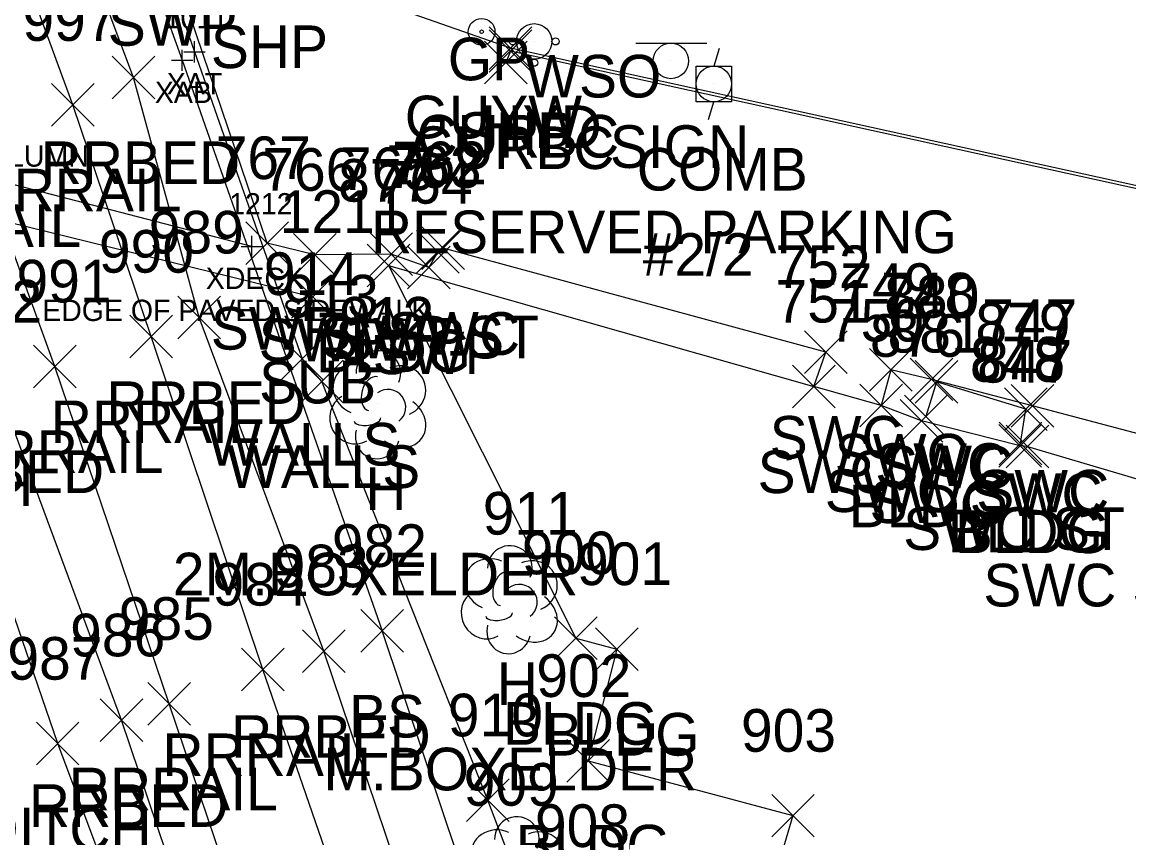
# Model space of a CAD drawing. Extents: x 1462668 to 1465147, y 550359 to 557351.
# Drawn here: x 1464802.6 to 1464854.5, y 552350.4 to 552388.6 of the extents above; entities that cross this region are included whole.
import ezdxf

# ---------------------------------------------------------------- set-up
doc = ezdxf.new("R2010")
doc.units = 0
for name, color, linetype in [('B_A', 7, 'Continuous'), ('B_C', 7, 'Continuous'), ('B_I', 7, 'Continuous'), ('B_TIC', 7, 'Continuous'), ('BELB', 7, 'Continuous'), ('BSUBM', 7, 'Continuous'), ('D_A', 7, 'Continuous'), ('D_I', 7, 'Continuous'), ('D_TIC', 7, 'Continuous'), ('DD', 7, 'Continuous'), ('L_A', 7, 'Continuous'), ('L_C', 7, 'Continuous'), ('L_I', 7, 'Continuous'), ('L_TIC', 7, 'Continuous'), ('LBC', 7, 'Continuous'), ('LELB', 7, 'Continuous'), ('LTD', 7, 'Continuous'), ('LWS', 7, 'Continuous'), ('P_A', 7, 'Continuous'), ('P_TIC', 7, 'Continuous'), ('PSP', 7, 'Continuous'), ('R_A', 7, 'Continuous'), ('R_I', 7, 'Continuous'), ('R_TIC', 7, 'Continuous'), ('RC', 7, 'Continuous'), ('RR', 7, 'Continuous'), ('RRB', 7, 'Continuous'), ('RSW', 7, 'Continuous'), ('S_A', 7, 'Continuous'), ('S_C', 7, 'Continuous'), ('SSGN', 7, 'Continuous'), ('U_A', 7, 'Continuous'), ('U_C', 7, 'Continuous'), ('U_I', 7, 'Continuous'), ('U_TIC', 7, 'Continuous'), ('UP', 7, 'Continuous'), ('UPGW', 7, 'Continuous'), ('UUU', 7, 'Continuous'), ('UWFH', 7, 'Continuous')]:
    doc.layers.add(name, color=color, linetype=linetype)

msp = doc.modelspace()

# ---------------------------------------------------------------- linework, layer by layer
at = {"layer": 'B_TIC'}
for p, q in [((1464810.703, 552387.236), (1464810.778, 552387.236)), ((1464810.127, 552386.833), (1464810.203, 552386.833)), ((1464813.397, 552378.102), (1464813.472, 552378.102))]:
    msp.add_line(p, q, dxfattribs=at)
for points in [[(1464810.699, 552386.736), (1464810.699, 552387.736)], [(1464810.124, 552386.333), (1464810.124, 552387.333)], [(1464810.199, 552387.236), (1464811.199, 552387.236)], [(1464809.624, 552386.833), (1464810.624, 552386.833)], [(1464813.393, 552377.602), (1464813.393, 552378.602)], [(1464812.893, 552378.102), (1464813.893, 552378.102)]]:
    msp.add_lwpolyline(points, dxfattribs=at)
at = {"layer": 'BELB'}
msp.add_lwpolyline([(1464813.393, 552378.102), (1464799.823, 552381.621), (1464785.51, 552385.077)], dxfattribs=at)
at = {"layer": 'BSUBM'}
for points in [[(1464775.683, 552477.42), (1464775.939, 552477.572), (1464781.431, 552465.945), (1464796.582, 552427.88), (1464810.699, 552387.236)], [(1464775.683, 552477.42), (1464795.526, 552427.291), (1464810.124, 552386.833)], [(1464810.699, 552387.236), (1464815.756, 552372.822)], [(1464810.124, 552386.833), (1464819.514, 552360.064)]]:
    msp.add_lwpolyline(points, dxfattribs=at)
at = {"layer": 'D_TIC'}
for points in [[(1464803.285, 552353.776), (1464805.285, 552355.776)], [(1464805.285, 552353.776), (1464803.285, 552355.776)]]:
    msp.add_lwpolyline(points, dxfattribs=at)
at = {"layer": 'DD'}
msp.add_lwpolyline([(1464838.938, 552245.842), (1464832.309, 552266.963), (1464825.398, 552292.253), (1464817.853, 552318.608), (1464804.285, 552354.776), (1464798.736, 552370.918), (1464794.981, 552381.157)], dxfattribs=at)
at = {"layer": 'L_TIC'}
for points in [[(1464818.808, 552376.202), (1464820.808, 552378.202)], [(1464820.808, 552376.202), (1464818.808, 552378.202)], [(1464814.756, 552371.822), (1464816.756, 552373.822)], [(1464816.756, 552371.822), (1464814.756, 552373.822)], [(1464815.686, 552370.77), (1464817.686, 552372.77)], [(1464817.686, 552370.77), (1464815.686, 552372.77)], [(1464843.815, 552368.925), (1464845.815, 552370.925)], [(1464845.815, 552368.925), (1464843.815, 552370.925)], [(1464848.453, 552367.748), (1464850.453, 552369.748)], [(1464850.453, 552367.748), (1464848.453, 552369.748)], [(1464848.793, 552367.713), (1464850.793, 552369.713)], [(1464850.793, 552367.713), (1464848.793, 552369.713)], [(1464818.514, 552359.064), (1464820.514, 552361.064)], [(1464820.514, 552359.064), (1464818.514, 552361.064)], [(1464827.593, 552358.721), (1464829.593, 552360.721)], [(1464829.593, 552358.721), (1464827.593, 552360.721)], [(1464829.526, 552358.213), (1464831.526, 552360.213)], [(1464831.526, 552358.213), (1464829.526, 552360.213)], [(1464828.183, 552352.965), (1464830.183, 552354.965)], [(1464830.183, 552352.965), (1464828.183, 552354.965)], [(1464823.474, 552351.117), (1464825.474, 552353.117)], [(1464825.474, 552351.117), (1464823.474, 552353.117)], [(1464837.788, 552350.396), (1464839.788, 552352.396)], [(1464839.788, 552350.396), (1464837.788, 552352.396)]]:
    msp.add_lwpolyline(points, dxfattribs=at)
at = {"layer": 'LBC'}
for points in [[(1464819.808, 552377.202), (1464828.593, 552359.721), (1464830.526, 552359.213), (1464829.183, 552353.965), (1464838.788, 552351.396), (1464836.379, 552343.209), (1464841.14, 552341.464)], [(1464819.808, 552377.202), (1464839.766, 552371.53)], [(1464844.815, 552369.925), (1464842.92, 552370.641)], [(1464849.793, 552368.713), (1464849.453, 552368.748), (1464844.815, 552369.925)], [(1464849.793, 552368.713), (1464858.257, 552366.213)]]:
    msp.add_lwpolyline(points, dxfattribs=at)
at = {"layer": 'LELB'}
msp.add_lwpolyline([(1464854.329, 552250.98), (1464847.618, 552272.797), (1464840.374, 552296.612), (1464833.437, 552323.254), (1464825.847, 552341.173), (1464819.514, 552360.064)], dxfattribs=at)
at = {"layer": 'LTD'}
for p, q in [((1464819.287, 552370.731), (1464819.287, 552370.731)), ((1464819.287, 552370.731), (1464819.287, 552370.731)), ((1464825.458, 552361.583), (1464825.458, 552361.583)), ((1464825.458, 552361.583), (1464825.458, 552361.583))]:
    msp.add_line(p, q, dxfattribs=at)
for centre in [(1464819.333, 552372.165), (1464825.505, 552363.017), (1464825.83, 552350.298)]:
    msp.add_arc(centre, 1.047, 335.5272, 180.9563, dxfattribs=at)
for centre, major_axis, ratio, start_param, end_param in [((1464818.495, 552371.398), (1.21, -0.512), 0.895232, 1.570796, 4.712389), ((1464820.328, 552371.315), (-1.141, -0.483), 0.949671, 1.570796, 4.712389), ((1464819.078, 552371.19), (-0.208, -0.792), 0.645439, 3.141593, 6.283185), ((1464818.203, 552370.023), (0.584, -1.042), 0.959034, 3.141593, 6.283185), ((1464819.787, 552370.565), (-0.5, 0.667), 0.989748, 3.141593, 6.283185), ((1464820.287, 552369.898), (-1.09, 0.792), 0.841452, 1.570796, 4.712389), ((1464818.828, 552369.981), (-0.625, -0.083), 0.423636, 0, 3.141593), ((1464819.287, 552369.231), (0.265, 1.061), 0.942809, 1.570796, 4.712389), ((1464824.666, 552362.25), (1.21, -0.512), 0.895232, 1.570796, 4.712389), ((1464826.5, 552362.167), (-1.141, -0.483), 0.949671, 1.570796, 4.712389), ((1464825.25, 552362.041), (-0.208, -0.792), 0.645439, 3.141593, 6.283185), ((1464825.958, 552361.417), (-0.5, 0.667), 0.989748, 3.141593, 6.283185), ((1464824.375, 552360.875), (0.584, -1.042), 0.959034, 3.141593, 6.283185), ((1464826.458, 552360.75), (-1.09, 0.792), 0.841452, 1.570796, 4.712389), ((1464825, 552360.833), (-0.625, -0.083), 0.423636, 0, 3.141593), ((1464825.458, 552360.083), (0.265, 1.061), 0.942809, 1.570796, 4.712389), ((1464824.991, 552349.53), (1.21, -0.512), 0.895232, 1.570796, 4.712389), ((1464826.825, 552349.447), (-1.141, -0.483), 0.949671, 1.570796, 4.712389)]:
    msp.add_ellipse(centre, major_axis=major_axis, ratio=ratio, start_param=start_param, end_param=end_param, dxfattribs=at)
at = {"layer": 'LWS'}
msp.add_lwpolyline([(1464855.198, 552255.3), (1464847.558, 552276.515), (1464841.664, 552299.914), (1464835.533, 552322.98), (1464835.365, 552323.51), (1464828.08, 552342.622), (1464824.474, 552352.117), (1464816.686, 552371.77), (1464815.756, 552372.822)], dxfattribs=at)
at = {"layer": 'P_TIC'}
for points in [[(1464824.527, 552386.397), (1464826.527, 552388.397)], [(1464826.527, 552386.397), (1464824.527, 552388.397)]]:
    msp.add_lwpolyline(points, dxfattribs=at)
at = {"layer": 'PSP'}
msp.add_lwpolyline([(1464948.464, 552361.284), (1464924.269, 552366.192), (1464895.316, 552372.264), (1464865.11, 552378.716), (1464825.527, 552387.397), (1464813.937, 552391.469)], dxfattribs=at)
at = {"layer": 'R_TIC'}
for points in [[(1464824.539, 552386.27), (1464826.539, 552388.27)], [(1464826.539, 552386.27), (1464824.539, 552388.27)], [(1464824.315, 552385.733), (1464826.315, 552387.733)], [(1464826.315, 552385.733), (1464824.315, 552387.733)], [(1464806.843, 552385.028), (1464808.843, 552387.028)], [(1464808.843, 552385.028), (1464806.843, 552387.028)], [(1464803.992, 552383.746), (1464805.992, 552385.746)], [(1464805.992, 552383.746), (1464803.992, 552385.746)], [(1464813.11, 552377.261), (1464815.11, 552379.261)], [(1464815.11, 552377.261), (1464813.11, 552379.261)], [(1464821.12, 552376.849), (1464823.12, 552378.849)], [(1464823.12, 552376.849), (1464821.12, 552378.849)], [(1464821.378, 552377.018), (1464823.378, 552379.018)], [(1464823.378, 552377.018), (1464821.378, 552379.018)], [(1464815.353, 552376.713), (1464817.353, 552378.713)], [(1464817.353, 552376.713), (1464815.353, 552378.713)], [(1464818.941, 552376.744), (1464820.941, 552378.744)], [(1464820.941, 552376.744), (1464818.941, 552378.744)], [(1464820.704, 552376.109), (1464822.704, 552378.109)], [(1464822.704, 552376.109), (1464820.704, 552378.109)], [(1464809.928, 552373.769), (1464811.928, 552375.769)], [(1464811.928, 552373.769), (1464809.928, 552375.769)], [(1464807.668, 552372.872), (1464809.668, 552374.872)], [(1464809.668, 552372.872), (1464807.668, 552374.872)], [(1464839.333, 552372.146), (1464841.333, 552374.146)], [(1464841.333, 552372.146), (1464839.333, 552374.146)], [(1464803.149, 552371.473), (1464805.149, 552373.473)], [(1464805.149, 552371.473), (1464803.149, 552373.473)], [(1464842.383, 552371.308), (1464844.383, 552373.308)], [(1464844.383, 552371.308), (1464842.383, 552373.308)], [(1464844.283, 552370.866), (1464846.283, 552372.866)], [(1464846.283, 552370.866), (1464844.283, 552372.866)], [(1464844.519, 552370.754), (1464846.519, 552372.754)], [(1464846.519, 552370.754), (1464844.519, 552372.754)], [(1464838.766, 552370.53), (1464840.766, 552372.53)], [(1464840.766, 552370.53), (1464838.766, 552372.53)], [(1464841.92, 552369.641), (1464843.92, 552371.641)], [(1464843.92, 552369.641), (1464841.92, 552371.641)], [(1464849.027, 552369.62), (1464851.027, 552371.62)], [(1464851.027, 552369.62), (1464849.027, 552371.62)], [(1464844.021, 552369.124), (1464846.021, 552371.124)], [(1464846.021, 552369.124), (1464844.021, 552371.124)], [(1464848.716, 552369.461), (1464850.716, 552371.461)], [(1464850.716, 552369.461), (1464848.716, 552371.461)], [(1464848.463, 552367.862), (1464850.463, 552369.862)], [(1464850.463, 552367.862), (1464848.463, 552369.862)], [(1464815.78, 552358.11), (1464817.78, 552360.11)], [(1464817.78, 552358.11), (1464815.78, 552360.11)], [(1464812.909, 552357.251), (1464814.909, 552359.251)], [(1464814.909, 552357.251), (1464812.909, 552359.251)], [(1464808.517, 552355.645), (1464810.517, 552357.645)], [(1464810.517, 552355.645), (1464808.517, 552357.645)], [(1464806.286, 552354.87), (1464808.286, 552356.87)], [(1464808.286, 552354.87), (1464806.286, 552356.87)]]:
    msp.add_lwpolyline(points, dxfattribs=at)
at = {"layer": 'RC'}
msp.add_lwpolyline([(1464948.184, 552360.613), (1464948.268, 552361.112), (1464924.278, 552366.019), (1464895.338, 552372.102), (1464864.961, 552378.598), (1464825.539, 552387.27), (1464825.315, 552386.733)], dxfattribs=at)
at = {"layer": 'RR'}
for points in [[(1464849.389, 552249.534), (1464842.819, 552270.793), (1464835.11, 552294.838), (1464826.262, 552322.52), (1464813.909, 552358.251), (1464808.668, 552373.872), (1464804.992, 552384.746), (1464790.19, 552425.007), (1464777.181, 552458.665), (1464762.364, 552494.605), (1464744.909, 552535.145), (1464735.628, 552555.847), (1464721.293, 552586.6), (1464702.021, 552626.346), (1464686.842, 552656.687), (1464671.35, 552687.141), (1464662.335, 552704.74), (1464642.534, 552744.081), (1464629.159, 552771.135), (1464613.477, 552803.16), (1464601.343, 552828.316)], [(1464844.813, 552247.755), (1464838.177, 552269.149), (1464830.386, 552293.617), (1464821.392, 552321.548), (1464809.517, 552356.645), (1464804.149, 552372.473), (1464800.295, 552383.078), (1464785.596, 552423.206), (1464772.719, 552456.472), (1464757.811, 552492.705), (1464740.233, 552533.386), (1464731.218, 552553.662), (1464716.736, 552584.611), (1464697.665, 552624.112), (1464682.453, 552654.497), (1464666.878, 552684.945), (1464657.727, 552702.874), (1464638.134, 552741.98), (1464624.708, 552768.998), (1464609.228, 552800.971), (1464596.703, 552826.136)]]:
    msp.add_lwpolyline(points, dxfattribs=at)
at = {"layer": 'RRB'}
for points in [[(1464851.042, 552250.445), (1464845.147, 552271.635), (1464837.544, 552295.462), (1464828.768, 552323.575), (1464816.78, 552359.11), (1464810.928, 552374.769), (1464807.843, 552386.028), (1464792.774, 552426.038), (1464778.944, 552461.754), (1464771.168, 552477.614), (1464764.619, 552495.611), (1464747.04, 552536.302), (1464737.618, 552557.165), (1464723.44, 552587.94), (1464704.535, 552627.922), (1464689.191, 552657.618), (1464673.574, 552688.335), (1464664.014, 552705.151), (1464644.495, 552745.11), (1464631.556, 552772.375), (1464615.641, 552804.178), (1464603.908, 552829.416)], [(1464842.442, 552246.931), (1464836.486, 552268.553), (1464828.066, 552292.901), (1464819.091, 552320.895), (1464807.286, 552355.87), (1464801.457, 552371.532), (1464797.599, 552381.724), (1464783.012, 552422.471), (1464769.406, 552454.584), (1464755.315, 552491.81), (1464738.611, 552532.376), (1464729.391, 552552.755), (1464715, 552583.837), (1464695.071, 552622.976), (1464679.554, 552652.995), (1464663.948, 552683.282), (1464654.855, 552701.899), (1464635.344, 552740.456), (1464622.383, 552767.72), (1464607.066, 552799.752), (1464594.744, 552825)]]:
    msp.add_lwpolyline(points, dxfattribs=at)
at = {"layer": 'RSW'}
for points in [[(1464822.12, 552377.849), (1464821.704, 552377.109), (1464819.941, 552377.744), (1464816.353, 552377.713), (1464814.11, 552378.261), (1464809.275, 552392.519)], [(1464858.257, 552366.213), (1464858.936, 552368.259), (1464850.027, 552370.62), (1464845.283, 552371.866), (1464843.383, 552372.308), (1464842.92, 552370.641), (1464839.766, 552371.53), (1464840.333, 552373.146), (1464822.378, 552378.018)], [(1464849.463, 552368.862), (1464849.716, 552370.461), (1464845.519, 552371.754), (1464845.021, 552370.124)]]:
    msp.add_lwpolyline(points, dxfattribs=at)
at = {"layer": 'SSGN'}
for p, q in [((1464831.412, 552387.639), (1464834.745, 552387.639)), ((1464833.059, 552386.805), (1464833.059, 552386.805))]:
    msp.add_line(p, q, dxfattribs=at)
msp.add_circle((1464833.059, 552386.805), 0.833, dxfattribs=at)
at = {"layer": 'U_TIC'}
for points in [[(1464815.262, 552374.735), (1464817.262, 552376.735)], [(1464817.262, 552374.735), (1464815.262, 552376.735)]]:
    msp.add_lwpolyline(points, dxfattribs=at)
at = {"layer": 'UP'}
for p, q in [((1464835.324, 552387.39), (1464835.074, 552386.557)), ((1464834.241, 552384.89), (1464834.241, 552386.557)), ((1464834.241, 552386.557), (1464835.907, 552386.557)), ((1464835.907, 552386.557), (1464835.907, 552384.89)), ((1464835.074, 552385.724), (1464835.074, 552385.724)), ((1464835.907, 552384.89), (1464834.241, 552384.89)), ((1464834.824, 552384.057), (1464835.074, 552384.89))]:
    msp.add_line(p, q, dxfattribs=at)
msp.add_circle((1464835.074, 552385.724), 0.833, dxfattribs=at)
at = {"layer": 'UPGW'}
for radius in [0.625, 0.0833]:
    msp.add_circle((1464824.178, 552388.173), radius, dxfattribs=at)
at = {"layer": 'UUU'}
msp.add_lwpolyline([(1464785.653, 552383.262), (1464816.262, 552375.735)], dxfattribs=at)
at = {"layer": 'UWFH'}
msp.add_line((1464826.647, 552387.72), (1464826.647, 552387.72), dxfattribs=at)
for centre, radius in [((1464826.647, 552387.72), 0.833), ((1464825.647, 552387.72), 0.167), ((1464827.647, 552387.72), 0.167), ((1464826.647, 552386.72), 0.167)]:
    msp.add_circle(centre, radius, dxfattribs=at)

# ---------------------------------------------------------------- texts
at = {"layer": 'B_A'}
for s, p in [('XAT', (1464809.404, 552385.236)), ('XAB', (1464808.844, 552384.833)), ('XDECK', (1464811.236, 552376.102))]:
    msp.add_text(s, height=1, dxfattribs=at).set_placement(p)
at = {"layer": 'B_C'}
for s, p in [('CONC BASE W/500X300 CONC COLUMN', (1464780.034, 552381.844)), ('EDGE OF PAVED SIDEWALK', (1464803.559, 552374.602))]:
    msp.add_text(s, height=1, dxfattribs=at).set_placement(p)
at = {"layer": 'B_I'}
for s, p in [('1011', (1464809.305, 552388.333)), ('1212', (1464812.33, 552379.602))]:
    msp.add_text(s, height=1, dxfattribs=at).set_placement(p)
at = {"layer": 'D_A'}
for p in [(1464794.972, 552365.918), (1464800.521, 552349.776)]:
    msp.add_text('DITCH', height=2, dxfattribs=at).set_placement(p)
at = {"layer": 'D_I'}
msp.add_text('987', height=2, dxfattribs=at).set_placement((1464801.923, 552357.776))
at = {"layer": 'L_A'}
for s, p in [('BLDG', (1464816.399, 552372.202)), ('WALLS', (1464811.299, 552367.822)), ('WALLS', (1464812.229, 552366.77)), ('H', (1464818.72, 552365.731)), ('BLDG', (1464841.406, 552364.925)), ('BLDG', (1464846.043, 552363.748)), ('BLDG', (1464846.384, 552363.713)), ('H', (1464824.891, 552356.583)), ('BS', (1464817.955, 552355.064)), ('BLDG', (1464825.183, 552354.721)), ('BLDG', (1464827.117, 552354.213)), ('BLDG', (1464825.773, 552348.965))]:
    msp.add_text(s, height=2, dxfattribs=at).set_placement(p)
at = {"layer": 'L_C'}
for s, p in [('2M.BOXELDER', (1464809.688, 552361.731)), ('M.BOXELDER', (1464816.757, 552352.583))]:
    msp.add_text(s, height=2, dxfattribs=at).set_placement(p)
at = {"layer": 'L_I'}
for s, p in [('877', (1464817.446, 552380.202)), ('914', (1464813.961, 552375.822)), ('913', (1464814.891, 552374.77)), ('912', (1464817.491, 552373.731)), ('876', (1464842.398, 552372.925)), ('848', (1464847.09, 552371.748)), ('847', (1464847.431, 552371.713)), ('911', (1464824.23, 552364.583)), ('982', (1464817.152, 552363.064)), ('900', (1464826.065, 552362.721)), ('901', (1464828.652, 552362.213)), ('902', (1464826.742, 552356.965)), ('910', (1464822.592, 552355.117)), ('903', (1464836.347, 552354.396)), ('909', (1464823.334, 552351.864)), ('908', (1464826.68, 552349.925))]:
    msp.add_text(s, height=2, dxfattribs=at).set_placement(p)
at = {"layer": 'P_A'}
for p in [(1464811.473, 552386.469), (1464823.062, 552382.397)]:
    msp.add_text('SHP', height=2, dxfattribs=at).set_placement(p)
at = {"layer": 'R_A'}
for s, p in [('SWP', (1464806.637, 552387.519)), ('GP', (1464822.591, 552385.895)), ('CURBC', (1464821.122, 552382.27)), ('CURBC', (1464820.898, 552381.733)), ('RRBED', (1464803.488, 552381.028)), ('RRRAIL', (1464800.284, 552379.746)), ('RRRAIL', (1464795.587, 552378.078)), ('SWP', (1464811.472, 552373.261)), ('SWP', (1464813.715, 552372.713)), ('SWP ST', (1464816.616, 552372.849)), ('SWP', (1464817.304, 552372.744)), ('SWC', (1464819.74, 552373.018)), ('SWP', (1464819.066, 552372.109)), ('RRBED', (1464806.573, 552369.769)), ('RRRAIL', (1464803.959, 552368.872)), ('SWC', (1464837.695, 552368.146)), ('RRRAIL', (1464799.44, 552367.473)), ('SWC', (1464840.745, 552367.308)), ('RRBED', (1464797.103, 552366.532)), ('SWC', (1464837.128, 552366.53)), ('SWC', (1464842.645, 552366.866)), ('SWC', (1464842.882, 552366.754)), ('SWC', (1464840.282, 552365.641)), ('SWC', (1464847.078, 552365.461)), ('SWC', (1464847.389, 552365.62)), ('SWC', (1464842.383, 552365.124)), ('SWC ST', (1464843.959, 552363.862)), ('SWC ST BLDG1', (1464847.722, 552361.213)), ('RRBED', (1464812.425, 552354.11)), ('RRRAIL', (1464809.2, 552353.251)), ('RRRAIL', (1464804.808, 552351.645)), ('RRBED', (1464802.932, 552350.87))]:
    msp.add_text(s, height=2, dxfattribs=at).set_placement(p)
at = {"layer": 'R_I'}
for s, p in [('997', (1464802.63, 552387.746)), ('767', (1464811.7, 552381.261)), ('762', (1464819.969, 552381.018)), ('766', (1464813.888, 552380.713)), ('765', (1464817.532, 552380.744)), ('763', (1464819.71, 552380.849)), ('764', (1464819.294, 552380.109)), ('989', (1464808.558, 552377.769)), ('990', (1464806.219, 552376.872)), ('752', (1464837.97, 552376.146)), ('991', (1464802.353, 552375.473)), ('749', (1464841.013, 552375.308)), ('748', (1464842.921, 552374.866)), ('880', (1464843.071, 552374.754)), ('992', (1464799.095, 552374.532)), ('751', (1464837.971, 552374.53)), ('750', (1464840.471, 552373.641)), ('879', (1464847.346, 552373.461)), ('747', (1464847.665, 552373.62)), ('881', (1464843.226, 552373.124)), ('878', (1464847.1, 552371.862)), ('983', (1464814.417, 552362.11)), ('984', (1464811.547, 552361.251)), ('985', (1464807.154, 552359.645)), ('986', (1464804.869, 552358.87))]:
    msp.add_text(s, height=2, dxfattribs=at).set_placement(p)
at = {"layer": 'S_A'}
msp.add_text('SIGN', height=2, dxfattribs=at).set_placement((1464830.196, 552381.785))
at = {"layer": 'S_C'}
msp.add_text('RESERVED PARKING', height=2, dxfattribs=at).set_placement((1464818.984, 552377.785))
at = {"layer": 'U_A'}
for s, p in [('WSO', (1464826.22, 552385.09)), ('GUYW', (1464820.571, 552383.173)), ('HYD', (1464824.167, 552382.72)), ('COMB', (1464831.46, 552380.724)), ('SUB', (1464813.735, 552370.735))]:
    msp.add_text(s, height=2, dxfattribs=at).set_placement(p)
at = {"layer": 'U_C'}
msp.add_text('#2/2', height=2, dxfattribs=at).set_placement((1464831.736, 552376.724))
at = {"layer": 'U_I'}
msp.add_text('1211', height=2, dxfattribs=at).set_placement((1464814.703, 552378.735))

doc.saveas('drawing.dxf')
